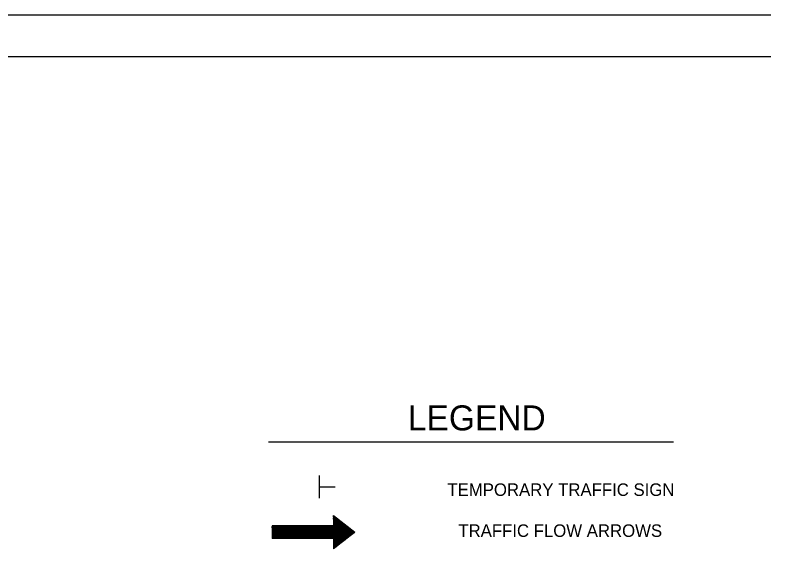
# Model space of a CAD drawing. Extents: x -160 to 6143532, y -375 to 762199.
# Drawn here: x -54.93 to -22.61, y 50.65 to 73.48 of the extents above; entities that cross this region are included whole.
import ezdxf

# ---------------------------------------------------------------- set-up
doc = ezdxf.new("R2010")
doc.units = 0
for name, color, linetype in [('Level 3', 7, 'Continuous'), ('R_Annotation', 7, 'Continuous'), ('R_Draft', 7, 'Continuous')]:
    doc.layers.add(name, color=color, linetype=linetype)

msp = doc.modelspace()

# ---------------------------------------------------------------- linework, layer by layer
at = {"layer": 'Level 3'}
for p, q in [((-41.918, 52.82), (-41.918, 53.784)), ((-41.904, 53.3), (-41.246, 53.3))]:
    msp.add_line(p, q, dxfattribs=at)
at = {"layer": 'R_Annotation'}
for p, q in [((-44.088, 55.226), (-26.779, 55.226)), ((-41.318, 52.067), (-41.314, 52.072)), ((-41.318, 52.054), (-41.307, 52.066)), ((-41.318, 52.042), (-41.3, 52.061)), ((-41.318, 52.029), (-41.292, 52.055)), ((-41.318, 52.017), (-41.285, 52.05)), ((-41.318, 52.004), (-41.278, 52.044)), ((-41.318, 51.991), (-41.271, 52.039)), ((-41.848, 51.096), (-41.064, 51.879)), ((-41.835, 51.096), (-41.057, 51.874)), ((-41.823, 51.096), (-41.05, 51.868)), ((-41.81, 51.096), (-41.043, 51.863)), ((-41.797, 51.096), (-41.036, 51.857)), ((-41.785, 51.096), (-41.029, 51.852)), ((-41.772, 51.096), (-41.022, 51.846)), ((-41.759, 51.096), (-41.014, 51.841)), ((-41.747, 51.096), (-41.007, 51.835)), ((-41.734, 51.096), (-41, 51.83)), ((-41.722, 51.096), (-40.993, 51.824)), ((-41.709, 51.096), (-40.986, 51.819)), ((-41.696, 51.096), (-40.979, 51.813)), ((-41.684, 51.096), (-40.972, 51.808)), ((-41.671, 51.096), (-40.964, 51.802)), ((-41.659, 51.096), (-40.957, 51.797)), ((-41.646, 51.096), (-40.95, 51.791)), ((-41.633, 51.096), (-40.943, 51.786)), ((-41.621, 51.096), (-40.936, 51.78)), ((-41.608, 51.096), (-40.929, 51.775)), ((-41.595, 51.096), (-40.922, 51.769)), ((-41.583, 51.096), (-40.915, 51.764)), ((-41.57, 51.096), (-40.907, 51.758)), ((-41.558, 51.096), (-40.9, 51.753)), ((-41.545, 51.096), (-40.893, 51.747)), ((-41.532, 51.096), (-40.886, 51.742)), ((-41.52, 51.096), (-40.879, 51.736)), ((-41.507, 51.096), (-40.872, 51.731)), ((-41.494, 51.096), (-40.865, 51.725)), ((-41.482, 51.096), (-40.858, 51.72)), ((-41.469, 51.096), (-40.85, 51.714)), ((-41.318, 51.979), (-41.264, 52.033)), ((-41.318, 51.966), (-41.257, 52.028)), ((-41.318, 51.953), (-41.25, 52.022)), ((-41.318, 51.941), (-41.243, 52.017)), ((-41.318, 51.928), (-41.235, 52.011)), ((-41.318, 51.916), (-41.228, 52.006)), ((-41.318, 51.903), (-41.221, 52)), ((-41.318, 51.89), (-41.214, 51.995)), ((-41.318, 51.878), (-41.207, 51.989)), ((-41.318, 51.865), (-41.2, 51.984)), ((-41.318, 51.852), (-41.193, 51.978)), ((-41.318, 51.84), (-41.185, 51.973)), ((-41.318, 51.827), (-41.178, 51.967)), ((-41.318, 51.815), (-41.171, 51.962)), ((-41.318, 51.802), (-41.164, 51.956)), ((-41.318, 51.789), (-41.157, 51.951)), ((-41.318, 51.777), (-41.15, 51.945)), ((-41.318, 51.764), (-41.143, 51.94)), ((-41.318, 51.751), (-41.136, 51.934)), ((-41.318, 51.739), (-41.128, 51.929)), ((-41.318, 51.726), (-41.121, 51.923)), ((-41.318, 51.714), (-41.114, 51.918)), ((-41.318, 51.701), (-41.107, 51.912)), ((-41.318, 51.688), (-41.1, 51.907)), ((-41.318, 51.676), (-41.093, 51.901)), ((-41.318, 51.663), (-41.086, 51.896)), ((-41.318, 51.65), (-41.079, 51.89)), ((-41.318, 51.638), (-41.071, 51.885)), ((-43.938, 51.101), (-43.409, 51.63)), ((-43.938, 51.114), (-43.422, 51.63)), ((-43.938, 51.126), (-43.434, 51.63)), ((-43.938, 51.139), (-43.447, 51.63)), ((-43.938, 51.152), (-43.46, 51.63)), ((-43.938, 51.164), (-43.472, 51.63)), ((-43.938, 51.177), (-43.485, 51.63)), ((-43.938, 51.189), (-43.498, 51.63)), ((-43.938, 51.202), (-43.51, 51.63)), ((-43.938, 51.215), (-43.523, 51.63)), ((-43.938, 51.227), (-43.535, 51.63)), ((-43.938, 51.24), (-43.548, 51.63)), ((-43.938, 51.253), (-43.561, 51.63)), ((-43.938, 51.265), (-43.573, 51.63)), ((-43.938, 51.278), (-43.586, 51.63)), ((-43.938, 51.29), (-43.599, 51.63)), ((-43.938, 51.303), (-43.611, 51.63)), ((-43.938, 51.316), (-43.624, 51.63)), ((-43.938, 51.328), (-43.636, 51.63)), ((-43.938, 51.341), (-43.649, 51.63)), ((-43.938, 51.354), (-43.662, 51.63)), ((-43.938, 51.366), (-43.674, 51.63)), ((-43.938, 51.379), (-43.687, 51.63)), ((-43.938, 51.391), (-43.7, 51.63)), ((-43.938, 51.404), (-43.712, 51.63)), ((-43.938, 51.417), (-43.725, 51.63)), ((-43.938, 51.429), (-43.737, 51.63)), ((-43.938, 51.442), (-43.75, 51.63)), ((-43.938, 51.455), (-43.763, 51.63)), ((-43.938, 51.467), (-43.775, 51.63)), ((-43.938, 51.48), (-43.788, 51.63)), ((-43.938, 51.492), (-43.8, 51.63)), ((-43.938, 51.505), (-43.813, 51.63)), ((-43.938, 51.518), (-43.826, 51.63)), ((-43.938, 51.53), (-43.838, 51.63)), ((-43.938, 51.543), (-43.851, 51.63)), ((-43.938, 51.556), (-43.864, 51.63)), ((-43.938, 51.568), (-43.876, 51.63)), ((-43.938, 51.581), (-43.889, 51.63)), ((-43.938, 51.593), (-43.901, 51.63)), ((-43.938, 51.606), (-43.914, 51.63)), ((-43.938, 51.619), (-43.927, 51.63)), ((-43.931, 51.096), (-43.397, 51.63)), ((-43.918, 51.096), (-43.384, 51.63)), ((-43.905, 51.096), (-43.371, 51.63)), ((-43.893, 51.096), (-43.359, 51.63)), ((-43.88, 51.096), (-43.346, 51.63)), ((-43.868, 51.096), (-43.333, 51.63)), ((-43.855, 51.096), (-43.321, 51.63)), ((-43.842, 51.096), (-43.308, 51.63)), ((-43.83, 51.096), (-43.296, 51.63)), ((-43.817, 51.096), (-43.283, 51.63)), ((-43.805, 51.096), (-43.27, 51.63)), ((-43.792, 51.096), (-43.258, 51.63)), ((-43.779, 51.096), (-43.245, 51.63)), ((-43.767, 51.096), (-43.232, 51.63)), ((-43.754, 51.096), (-43.22, 51.63)), ((-43.741, 51.096), (-43.207, 51.63)), ((-43.729, 51.096), (-43.195, 51.63)), ((-43.716, 51.096), (-43.182, 51.63)), ((-43.704, 51.096), (-43.169, 51.63)), ((-43.691, 51.096), (-43.157, 51.63)), ((-43.678, 51.096), (-43.144, 51.63)), ((-43.666, 51.096), (-43.131, 51.63)), ((-43.653, 51.096), (-43.119, 51.63)), ((-43.64, 51.096), (-43.106, 51.63)), ((-43.628, 51.096), (-43.094, 51.63)), ((-43.615, 51.096), (-43.081, 51.63)), ((-43.603, 51.096), (-43.068, 51.63)), ((-43.59, 51.096), (-43.056, 51.63)), ((-43.577, 51.096), (-43.043, 51.63)), ((-43.565, 51.096), (-43.03, 51.63)), ((-43.552, 51.096), (-43.018, 51.63)), ((-43.539, 51.096), (-43.005, 51.63)), ((-43.527, 51.096), (-42.993, 51.63)), ((-43.514, 51.096), (-42.98, 51.63)), ((-43.502, 51.096), (-42.967, 51.63)), ((-43.489, 51.096), (-42.955, 51.63)), ((-43.476, 51.096), (-42.942, 51.63)), ((-43.464, 51.096), (-42.929, 51.63)), ((-43.451, 51.096), (-42.917, 51.63)), ((-43.438, 51.096), (-42.904, 51.63)), ((-43.426, 51.096), (-42.892, 51.63)), ((-43.413, 51.096), (-42.879, 51.63)), ((-43.401, 51.096), (-42.866, 51.63)), ((-43.388, 51.096), (-42.854, 51.63)), ((-43.375, 51.096), (-42.841, 51.63)), ((-43.363, 51.096), (-42.828, 51.63)), ((-43.35, 51.096), (-42.816, 51.63)), ((-43.337, 51.096), (-42.803, 51.63)), ((-43.325, 51.096), (-42.791, 51.63)), ((-43.312, 51.096), (-42.778, 51.63)), ((-43.3, 51.096), (-42.765, 51.63)), ((-43.287, 51.096), (-42.753, 51.63)), ((-43.274, 51.096), (-42.74, 51.63)), ((-43.262, 51.096), (-42.727, 51.63)), ((-43.249, 51.096), (-42.715, 51.63)), ((-43.236, 51.096), (-42.702, 51.63)), ((-43.224, 51.096), (-42.69, 51.63)), ((-43.211, 51.096), (-42.677, 51.63)), ((-43.199, 51.096), (-42.664, 51.63)), ((-43.186, 51.096), (-42.652, 51.63)), ((-43.173, 51.096), (-42.639, 51.63)), ((-43.161, 51.096), (-42.627, 51.63)), ((-43.148, 51.096), (-42.614, 51.63)), ((-43.135, 51.096), (-42.601, 51.63)), ((-43.123, 51.096), (-42.589, 51.63)), ((-43.11, 51.096), (-42.576, 51.63)), ((-43.098, 51.096), (-42.563, 51.63)), ((-43.085, 51.096), (-42.551, 51.63)), ((-43.072, 51.096), (-42.538, 51.63)), ((-43.06, 51.096), (-42.526, 51.63)), ((-43.047, 51.096), (-42.513, 51.63)), ((-43.034, 51.096), (-42.5, 51.63)), ((-43.022, 51.096), (-42.488, 51.63)), ((-43.009, 51.096), (-42.475, 51.63)), ((-42.997, 51.096), (-42.462, 51.63)), ((-42.984, 51.096), (-42.45, 51.63)), ((-42.971, 51.096), (-42.437, 51.63)), ((-42.959, 51.096), (-42.425, 51.63)), ((-42.946, 51.096), (-42.412, 51.63)), ((-42.933, 51.096), (-42.399, 51.63)), ((-42.921, 51.096), (-42.387, 51.63)), ((-42.908, 51.096), (-42.374, 51.63)), ((-42.896, 51.096), (-42.361, 51.63)), ((-42.883, 51.096), (-42.349, 51.63)), ((-42.87, 51.096), (-42.336, 51.63)), ((-42.858, 51.096), (-42.324, 51.63)), ((-42.845, 51.096), (-42.311, 51.63)), ((-42.832, 51.096), (-42.298, 51.63)), ((-42.82, 51.096), (-42.286, 51.63)), ((-42.807, 51.096), (-42.273, 51.63)), ((-42.795, 51.096), (-42.26, 51.63)), ((-42.782, 51.096), (-42.248, 51.63)), ((-42.769, 51.096), (-42.235, 51.63)), ((-42.757, 51.096), (-42.223, 51.63)), ((-42.744, 51.096), (-42.21, 51.63)), ((-42.732, 51.096), (-42.197, 51.63)), ((-42.719, 51.096), (-42.185, 51.63)), ((-42.706, 51.096), (-42.172, 51.63)), ((-42.694, 51.096), (-42.159, 51.63)), ((-42.681, 51.096), (-42.147, 51.63)), ((-42.668, 51.096), (-42.134, 51.63)), ((-42.656, 51.096), (-42.122, 51.63)), ((-42.643, 51.096), (-42.109, 51.63)), ((-42.631, 51.096), (-42.096, 51.63)), ((-42.618, 51.096), (-42.084, 51.63)), ((-42.605, 51.096), (-42.071, 51.63)), ((-42.593, 51.096), (-42.058, 51.63)), ((-42.58, 51.096), (-42.046, 51.63)), ((-42.567, 51.096), (-42.033, 51.63)), ((-42.555, 51.096), (-42.021, 51.63)), ((-42.542, 51.096), (-42.008, 51.63)), ((-42.53, 51.096), (-41.995, 51.63)), ((-42.517, 51.096), (-41.983, 51.63)), ((-42.504, 51.096), (-41.97, 51.63)), ((-42.492, 51.096), (-41.957, 51.63)), ((-42.479, 51.096), (-41.945, 51.63)), ((-42.466, 51.096), (-41.932, 51.63)), ((-42.454, 51.096), (-41.92, 51.63)), ((-42.441, 51.096), (-41.907, 51.63)), ((-42.429, 51.096), (-41.894, 51.63)), ((-42.416, 51.096), (-41.882, 51.63)), ((-42.403, 51.096), (-41.869, 51.63)), ((-42.391, 51.096), (-41.856, 51.63)), ((-42.378, 51.096), (-41.844, 51.63)), ((-42.365, 51.096), (-41.831, 51.63)), ((-42.353, 51.096), (-41.819, 51.63)), ((-42.34, 51.096), (-41.806, 51.63)), ((-42.328, 51.096), (-41.793, 51.63)), ((-42.315, 51.096), (-41.781, 51.63)), ((-42.302, 51.096), (-41.768, 51.63)), ((-42.29, 51.096), (-41.755, 51.63)), ((-42.277, 51.096), (-41.743, 51.63)), ((-42.264, 51.096), (-41.73, 51.63)), ((-42.252, 51.096), (-41.718, 51.63)), ((-42.239, 51.096), (-41.705, 51.63)), ((-42.227, 51.096), (-41.692, 51.63)), ((-42.214, 51.096), (-41.68, 51.63)), ((-42.201, 51.096), (-41.667, 51.63)), ((-42.189, 51.096), (-41.654, 51.63)), ((-42.176, 51.096), (-41.642, 51.63)), ((-42.163, 51.096), (-41.629, 51.63)), ((-42.151, 51.096), (-41.617, 51.63)), ((-42.138, 51.096), (-41.604, 51.63)), ((-42.126, 51.096), (-41.591, 51.63)), ((-42.113, 51.096), (-41.579, 51.63)), ((-42.1, 51.096), (-41.566, 51.63)), ((-42.088, 51.096), (-41.554, 51.63)), ((-42.075, 51.096), (-41.541, 51.63)), ((-42.062, 51.096), (-41.528, 51.63)), ((-42.05, 51.096), (-41.516, 51.63)), ((-42.037, 51.096), (-41.503, 51.63)), ((-42.025, 51.096), (-41.49, 51.63)), ((-42.012, 51.096), (-41.478, 51.63)), ((-41.999, 51.096), (-41.465, 51.63)), ((-41.987, 51.096), (-41.453, 51.63)), ((-41.974, 51.096), (-41.44, 51.63)), ((-41.961, 51.096), (-41.427, 51.63)), ((-41.949, 51.096), (-41.415, 51.63)), ((-41.936, 51.096), (-41.402, 51.63)), ((-41.924, 51.096), (-41.389, 51.63)), ((-41.911, 51.096), (-41.377, 51.63)), ((-41.898, 51.096), (-41.364, 51.63)), ((-41.886, 51.096), (-41.352, 51.63)), ((-41.873, 51.096), (-41.339, 51.63)), ((-41.86, 51.096), (-41.326, 51.63)), ((-41.457, 51.096), (-40.843, 51.709)), ((-41.444, 51.096), (-40.836, 51.703)), ((-41.431, 51.096), (-40.829, 51.698)), ((-41.419, 51.096), (-40.822, 51.693)), ((-41.406, 51.096), (-40.815, 51.687)), ((-41.393, 51.096), (-40.808, 51.682)), ((-41.381, 51.096), (-40.8, 51.676)), ((-41.368, 51.096), (-40.793, 51.671)), ((-41.356, 51.096), (-40.786, 51.665)), ((-41.343, 51.096), (-40.779, 51.66)), ((-41.33, 51.096), (-40.772, 51.654)), ((-41.318, 51.095), (-40.765, 51.649)), ((-41.318, 51.082), (-40.758, 51.643)), ((-41.318, 51.07), (-40.751, 51.638)), ((-41.318, 51.057), (-40.743, 51.632)), ((-41.318, 51.045), (-40.736, 51.627)), ((-41.318, 51.032), (-40.729, 51.621)), ((-41.318, 51.019), (-40.722, 51.616)), ((-41.318, 51.007), (-40.715, 51.61)), ((-41.318, 50.994), (-40.708, 51.605)), ((-41.318, 50.981), (-40.701, 51.599)), ((-41.318, 50.969), (-40.694, 51.594)), ((-41.318, 50.956), (-40.686, 51.588)), ((-41.318, 50.944), (-40.679, 51.583)), ((-41.318, 50.931), (-40.672, 51.577)), ((-41.318, 50.918), (-40.665, 51.572)), ((-41.318, 50.906), (-40.658, 51.566)), ((-41.318, 50.893), (-40.651, 51.561)), ((-41.318, 50.88), (-40.644, 51.555)), ((-41.318, 50.868), (-40.637, 51.55)), ((-41.318, 50.855), (-40.629, 51.544)), ((-41.318, 50.843), (-40.622, 51.539)), ((-41.318, 50.83), (-40.615, 51.533)), ((-41.318, 50.817), (-40.608, 51.528)), ((-41.318, 50.805), (-40.601, 51.522)), ((-41.318, 50.792), (-40.594, 51.517)), ((-41.318, 50.779), (-40.587, 51.511)), ((-41.318, 50.767), (-40.579, 51.506)), ((-41.318, 50.754), (-40.572, 51.5)), ((-41.318, 50.742), (-40.565, 51.495)), ((-41.318, 50.729), (-40.558, 51.489)), ((-41.318, 50.716), (-40.551, 51.484)), ((-41.318, 50.704), (-40.544, 51.478)), ((-41.318, 50.691), (-40.537, 51.473)), ((-41.318, 50.678), (-40.53, 51.467)), ((-41.318, 50.666), (-40.522, 51.462)), ((-41.318, 50.653), (-40.515, 51.456)), ((-41.275, 50.684), (-40.508, 51.451)), ((-41.22, 50.726), (-40.501, 51.445)), ((-41.165, 50.769), (-40.494, 51.44)), ((-41.11, 50.811), (-40.487, 51.434)), ((-41.055, 50.854), (-40.48, 51.429)), ((-41, 50.896), (-40.473, 51.423)), ((-40.945, 50.938), (-40.465, 51.418)), ((-40.89, 50.981), (-40.458, 51.412)), ((-40.835, 51.023), (-40.451, 51.407)), ((-40.78, 51.066), (-40.444, 51.401)), ((-40.725, 51.108), (-40.437, 51.396)), ((-40.67, 51.15), (-40.43, 51.39)), ((-40.615, 51.193), (-40.423, 51.385)), ((-40.56, 51.235), (-40.415, 51.379)), ((-40.505, 51.278), (-40.408, 51.374)), ((-40.45, 51.32), (-40.401, 51.368)), ((-40.394, 51.362), (-40.394, 51.363))]:
    msp.add_line(p, q, dxfattribs=at)
at = {"layer": 'R_Draft'}
for p, q in [((-22.609, 73.482), (-83.854, 73.482)), ((-22.609, 71.701), (-83.854, 71.701)), ((-41.318, 52.075), (-41.318, 51.63)), ((-41.318, 52.075), (-40.394, 51.363)), ((-41.318, 52.075), (-41.318, 51.63)), ((-41.318, 52.075), (-40.394, 51.363)), ((-41.318, 51.63), (-43.938, 51.63)), ((-43.938, 51.63), (-43.938, 51.096)), ((-41.318, 51.63), (-43.938, 51.63)), ((-43.938, 51.63), (-43.938, 51.096)), ((-41.318, 51.096), (-43.938, 51.096)), ((-41.318, 51.096), (-43.938, 51.096)), ((-40.394, 51.363), (-41.318, 50.651)), ((-40.394, 51.363), (-41.318, 50.651)), ((-41.318, 51.096), (-41.318, 50.651)), ((-41.318, 51.096), (-41.318, 50.651))]:
    msp.add_line(p, q, dxfattribs=at)

# ---------------------------------------------------------------- texts
at = {"layer": 'R_Annotation'}
for s, height, rotation, p in [('LEGEND', 1.0711, 0, (-38.129, 55.718)), ('TEMPORARY TRAFFIC SIGN', 0.53557, 360, (-36.442, 52.916)), ('TRAFFIC FLOW ARROWS', 0.53557, 360, (-35.974, 51.163))]:
    msp.add_text(s, height=height, rotation=rotation, dxfattribs=at).set_placement(p)

doc.saveas('drawing.dxf')
